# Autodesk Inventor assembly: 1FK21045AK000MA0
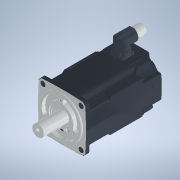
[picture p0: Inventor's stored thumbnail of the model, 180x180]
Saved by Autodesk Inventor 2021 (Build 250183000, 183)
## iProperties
Category: PARTsolutions
Created: 2026-06
Part Number: 1FK21045AK000MA0
Catalog Web Link: www.3dfindit.com
Description: 1FK21045AK000MA0-Servo synchronous motor
Document SubType Name: Assembly
Designer: psAdmin
Mass: 724.86 g
Surface Area: 1070.93 cm^2
Volume: 724.86 cm^3
Density: 1 g/cm^3
Title: 1FK21045AK000MA0
Author: Cadenas PARTsolutions
Comments: Servo synchronous motor
PSOL_IDENT_0: {$CADENAS_DATA/23d-libs/siemens_ag/_cat_/3d/2f/1fk21045ak000ma0.prj},193 {STYP=ASS},{VTYP=3D},{NB=1F
PSOL_IDENT_1: K21045AK000MA0},{LINA=1FK21045AK000MA0},{NN=1FK21045AK000MA0},{DATE=19.08.2025 14:00:34},{GEOMDATE=3
PSOL_IDENT_2: 0.07.2025 02:01:24},{VERSION=},{LINEID=10},{WBVAR=},{WBNUMERIC=}  {NB=1FK21045AK000MA0},{LINA=1FK210
PSOL_IDENT_3: 45AK000MA0},{KT=DUMMY},{PREVIEW=../../../_pool_/a9/69/p_d211_xx_00818j.png},{DESCSHORT=SIMOTICS S-1F
PSOL_IDENT_4: K2 HD, SINAMICS S210 3AC 400V-480V, 1.7 Nm, 6000 rpm},{DESCLONG=SIMOTICS S-1FK2 HD servo motor M0=2.
PSOL_IDENT_5: 4 Nm; PN = 1.07 kW at nN=6000 rpm (380-480 V); PN = 0.75 kW at nN=3000 rpm (200-240 V); degree of pr
PSOL_IDENT_6: otection IP64; cylindrical shaft D19x40mm; absolute encoder 22-bit + 12-bit multiturn (encoder AM22D
PSOL_IDENT_7: QC); with OCC interface; plug size M17, rotatable; SIMOTICS S-1FK2 servomotorfor a wide range of use
PSOL_IDENT_8: s in industrial environments. SIMOTICS S‑1FK2 servomotors are compact synchronous motors with a high
PSOL_IDENT_9: dynamic performance that set themselves apart as a result of their high power density, degree of pr
PSOL_IDENT_10: otection and overload capability. The motors are available in two variants: as High Dynamic variant
PSOL_IDENT_11: (highest dynamic performance as a result of the low intrinsic moment of inertia for applications dem
PSOL_IDENT_12: anding a high dynamic performance with low moved masses) - and as Compact variant (precise and stabl
PSOL_IDENT_13: e closed-loop control for medium up to large moved masses as a result of a medium intrinsic moment o
PSOL_IDENT_14: f inertia). SIMOTICSS‑1FK2 servomotors fully exploit their strengths in a system with the SINAMICSS2
PSOL_IDENT_15: 10 frequency converter and simple connection using the one cable connection (OCC). Advantages includ
PSOL_IDENT_16: e the short control and positioning times, fast and precise correction of disturbing quantities as w
PSOL_IDENT_17: ell as stable control with a high dynamic performance. The servo motors can be configured to address
PSOL_IDENT_18: a wide range of requirements. For example with and without holding brake, IP64 or IP65 degree of pr
PSOL_IDENT_19: otection, singleturn or multiturn absolute encoders - to name just a few. Further, the servomotors a
PSOL_IDENT_20: re available in different shaft heights extending from 20 to 100. A shaft sealing ring is available
PSOL_IDENT_21: to achieve an IP65 degree of protection and for subsequent mounting at the motor or as spare part. S
PSOL_IDENT_22: IMOTICS - the optimum motor for each and every motion control application.},{INTNO=804766789342},{SU
PSOL_IDENT_23: PPLIERALTNO=1FK2104-5AK00-0MA0},{MANUID=1FK21045AK000MA0},{MANUNAME=Siemens},{MANUTYPEDESC=Synchrono
PSOL_IDENT_24: us motor 1FK2-HD 2,39 Nm},{AAU732=SIMOTICS},{AAO057=S-1FK2},{AAU734=SIMOTICS S-1FK2 HD servo motor M
PSOL_IDENT_25: 0=2.4 Nm; PN = 1.07 kW at nN=6000 rpm (380-480 V); PN = 0.75 kW at nN=3000 rpm (200-240 V); degree o
PSOL_IDENT_26: f protection IP64; cylindrical shaft D19x40mm; absolute encoder 22-bit + 12-bit multiturn (encoder A
PSOL_IDENT_27: M22DQC); with OCC interface; plug size M17, rotatable;},{AAW338=Synchronous motor 1FK2-HD 2,39 Nm},{
PSOL_IDENT_28: AAO742=SIMOTICS},{AAO663=4042948691151},{NOCUPEROU=1},{PRICEQUANTITY=1},{QUANTITYMIN=1},{QUANTITYINT=
PSOL_IDENT_29: 1},{CTN=85015100},{COO=DE},{AAO676=1FK2104-5AK00-0MA0},{AAO677=Siemens AG},{ORDERUNIT=C62},{CONTENTU
PSOL_IDENT_30: NIT=C62}
NB: 1FK21045AK000MA0
NN: 1FK21045AK000MA0
NT: Servo synchronous motor
NBSYN: $MANUID.
LINA: 1FK21045AK000MA0
CATALOG: SIEMENS
PREVIEW: ../../../_pool_/a9/69/p_d211_xx_00818j.png
DESCSHORT: SIMOTICS S-1FK2 HD, SINAMICS S210 3AC 400V-480V, 1.7 Nm, 6000 rpm
DESCLONG: SIMOTICS S-1FK2 HD servo motor M0=2.4 Nm; PN = 1.07 kW at nN=6000 rpm (380-480 V); PN = 0.75 kW at nN=3000 rpm (200-240 V); degree of protection IP64; cylindric
INTNO: 804766789342
SUPPLIERALTNO: 1FK2104-5AK00-0MA0
MANUID: 1FK21045AK000MA0
MANUNAME: Siemens
MANUTYPEDESC: Synchronous motor 1FK2-HD 2,39 Nm
AAU732: SIMOTICS
AAO057: S-1FK2
AAU734: SIMOTICS S-1FK2 HD servo motor M0=2.4 Nm; PN = 1.07 kW at nN=6000 rpm (380-480 V); PN = 0.75 kW at nN=3000 rpm (200-240 V); degree of protection IP64; cylindric
AAW338: Synchronous motor 1FK2-HD 2,39 Nm
AAO742: SIMOTICS
AAO663: 4042948691151.0
NOCUPEROU: 1
PRICEQUANTITY: 1
QUANTITYMIN: 1
QUANTITYINT: 1
CTN: 85015100
COO: DE
ARTICLENO: 1FK21045AK000MA0
BOMINFO: 1FK21045AK000MA0
CREATOR: CADENAS GmbH
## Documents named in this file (24)
- e:\temp\worker_COMMON_19\temp\tmp_8776_8_8N72B\format_0\1FK21045AK000MA0.iam
- e:\temp\worker_COMMON_19\temp\tmp_8776_8_8N72B\format_0\1FK21045AK000MA0_PART1.ipt
- e:\temp\worker_COMMON_19\temp\tmp_8776_8_8N72B\format_0\1FK21045AK000MA0_PART2.ipt
- e:\temp\worker_COMMON_19\temp\tmp_8776_8_8N72B\format_0\1FK21045AK000MA0_PART3.ipt
- e:\temp\worker_COMMON_19\temp\tmp_8776_8_8N72B\format_0\1FK21045AK000MA0_PART4.ipt
- e:\temp\worker_COMMON_19\temp\tmp_8776_8_8N72B\format_0\1FK21045AK000MA0_PART5.ipt
- e:\temp\worker_COMMON_19\temp\tmp_8776_8_8N72B\format_0\1FK21045AK000MA0_PART6.ipt
- e:\temp\worker_COMMON_19\temp\tmp_8776_8_8N72B\format_0\1FK21045AK000MA0_PART7.ipt
- e:\temp\worker_COMMON_19\temp\tmp_8776_8_8N72B\format_0\1FK21045AK000MA0_PART8.ipt
- e:\temp\worker_COMMON_19\temp\tmp_8776_8_8N72B\format_0\1FK21045AK000MA0_PART9.ipt
- e:\temp\worker_COMMON_19\temp\tmp_8776_8_8N72B\format_0\1FK21045AK000MA0_PART10.ipt
- e:\temp\worker_COMMON_19\temp\tmp_8776_8_8N72B\format_0\1FK21045AK000MA0_PART11.ipt
- e:\temp\worker_COMMON_19\temp\tmp_8776_8_8N72B\format_0\1FK21045AK000MA0_PART12.ipt
- e:\temp\worker_COMMON_19\temp\tmp_8776_8_8N72B\format_0\1FK21045AK000MA0_PART13.ipt
- e:\temp\worker_COMMON_19\temp\tmp_8776_8_8N72B\format_0\1FK21045AK000MA0_PART14.ipt
- e:\temp\worker_COMMON_19\temp\tmp_8776_8_8N72B\format_0\1FK21045AK000MA0_PART15.ipt
- e:\temp\worker_COMMON_19\temp\tmp_8776_8_8N72B\format_0\1FK21045AK000MA0_PART16.ipt
- e:\temp\worker_COMMON_19\temp\tmp_8776_8_8N72B\format_0\1FK21045AK000MA0_PART17.ipt
- e:\temp\worker_COMMON_19\temp\tmp_8776_8_8N72B\format_0\1FK21045AK000MA0_PART18.ipt
- e:\temp\worker_COMMON_19\temp\tmp_8776_8_8N72B\format_0\1FK21045AK000MA0_PART19.ipt
- e:\temp\worker_COMMON_19\temp\tmp_8776_8_8N72B\format_0\1FK21045AK000MA0_PART20.ipt
- e:\temp\worker_COMMON_19\temp\tmp_8776_8_8N72B\format_0\1FK21045AK000MA0_PART21.ipt
- e:\temp\worker_COMMON_19\temp\tmp_8776_8_8N72B\format_0\1FK21045AK000MA0_PART22.ipt
- e:\temp\worker_COMMON_19\temp\tmp_8776_8_8N72B\format_0\1FK21045AK000MA0_PART23.ipt
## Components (23 placed, 23 different names)
1. 1FK21045AK000MA0_PART1:1
2. 1FK21045AK000MA0_PART2:1
3. 1FK21045AK000MA0_PART3:1
4. 1FK21045AK000MA0_PART4:1
5. 1FK21045AK000MA0_PART5:1
6. 1FK21045AK000MA0_PART6:1
7. 1FK21045AK000MA0_PART7:1
8. 1FK21045AK000MA0_PART8:1
9. 1FK21045AK000MA0_PART9:1
10. 1FK21045AK000MA0_PART10:1
11. 1FK21045AK000MA0_PART11:1
12. 1FK21045AK000MA0_PART12:1
13. 1FK21045AK000MA0_PART13:1
14. 1FK21045AK000MA0_PART14:1
15. 1FK21045AK000MA0_PART15:1
16. 1FK21045AK000MA0_PART16:1
17. 1FK21045AK000MA0_PART17:1
18. 1FK21045AK000MA0_PART18:1
19. 1FK21045AK000MA0_PART19:1
20. 1FK21045AK000MA0_PART20:1
21. 1FK21045AK000MA0_PART21:1
22. 1FK21045AK000MA0_PART22:1
23. 1FK21045AK000MA0_PART23:1
